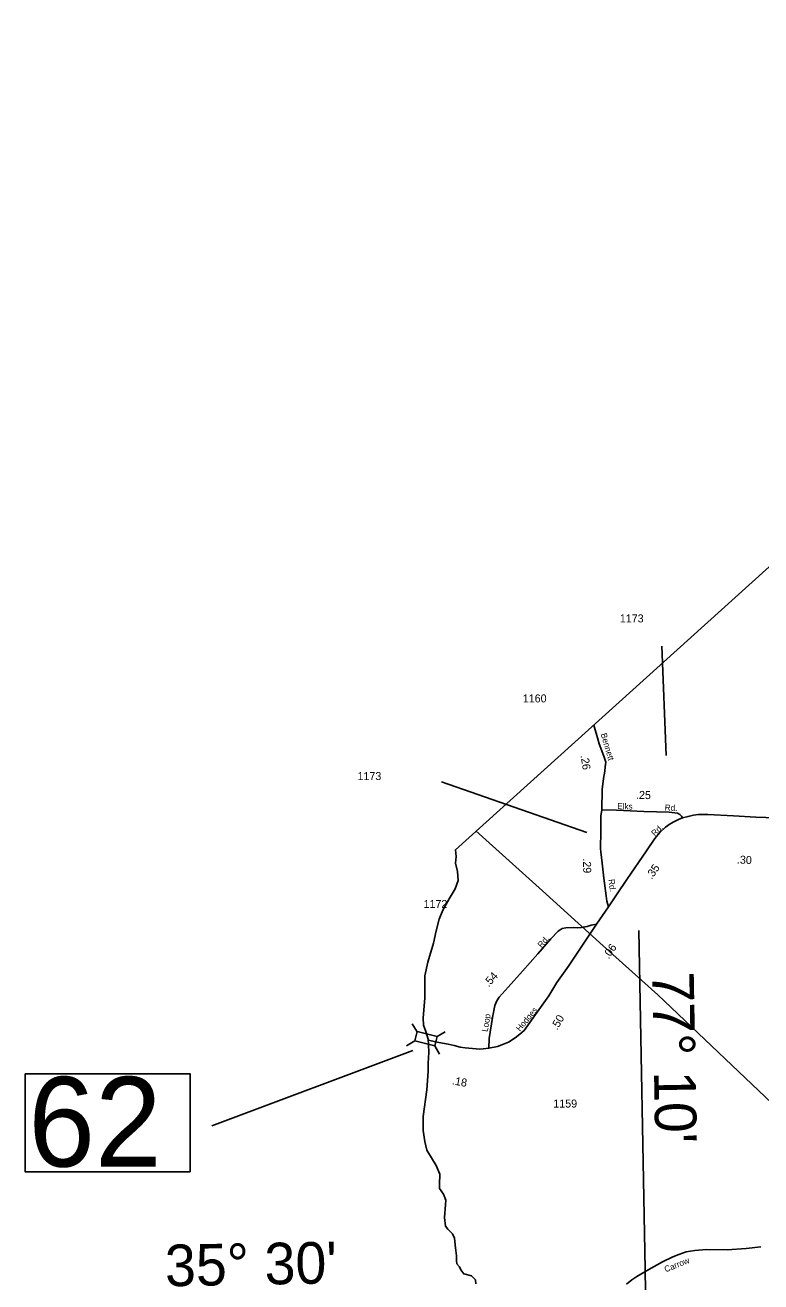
# Model space of a CAD drawing. Extents: x 2532689 to 2764727, y 536648 to 732970.
# Drawn here: x 2535937 to 2547433, y 642091 to 661725 of the extents above; entities that cross this region are included whole.
import ezdxf

# ---------------------------------------------------------------- set-up
doc = ezdxf.new("R2010")
doc.units = 0
for name, color, linetype in [('Exist Boundary Political CountyLine', 7, 'Continuous'), ('Exist Road Secondary Mileage Hundredths English Label', 7, 'Continuous'), ('Exist Road Secondary Structure Standard Bridge CELL', 7, 'Continuous'), ('Exist Road Secondary Structure Standard Bridge Number Label', 7, 'Continuous'), ('Exist Road Secondary Type 20 Attributed', 7, 'Continuous'), ('Exist Road Secondary Type 51 Attributed', 7, 'Continuous'), ('Exist Road Secondary Type 51 Label', 7, 'Continuous'), ('Exist Road Secondary Type 51 Number Label', 7, 'Continuous'), ('Exist Utilities Electrical Transmission Line', 7, 'Continuous'), ('Map Preparation Longitude Latitude Label', 7, 'Continuous'), ('Map Preparation Longitude Latitude Lines', 7, 'Continuous')]:
    doc.layers.add(name, color=color, linetype=linetype)

msp = doc.modelspace()

# ---------------------------------------------------------------- linework, layer by layer
at = {"layer": 'Exist Boundary Political CountyLine'}
for points in [[(2556945, 661725), (2542661, 648841)], [(2542661, 648841), (2542672, 648736), (2542664, 648632), (2542692, 648504), (2542702, 648360), (2542657, 648233), (2542562, 648076), (2542463, 647896), (2542407, 647759), (2542357, 647574), (2542316, 647383), (2542230, 647084), (2542183, 646875), (2542183, 646687), (2542184, 646527), (2542154, 646210), (2542160, 646100), (2542197, 646003), (2542232, 645884), (2542239, 645800), (2542243, 645676), (2542235, 645506), (2542235, 645376), (2542214, 645091), (2542154, 644674), (2542156, 644454), (2542181, 644283), (2542211, 644151), (2542357, 643910), (2542417, 643775), (2542409, 643611), (2542409, 643551), (2542473, 643459), (2542508, 643367), (2542504, 643295), (2542488, 643096), (2542504, 642964), (2542540, 642916), (2542616, 642844), (2542644, 642772), (2542660, 642624), (2542676, 642500), (2542676, 642424), (2542680, 642375), (2542725, 642326), (2542746, 642282), (2542790, 642217), (2542909, 642184), (2542972, 642124), (2542979, 642062)]]:
    msp.add_lwpolyline(points, dxfattribs=at)
at = {"layer": 'Exist Road Secondary Structure Standard Bridge CELL'}
for p, q in [((2542060, 645999), (2541984, 646125)), ((2542499, 645999), (2542373, 645923)), ((2542024, 645856), (2541898, 645781)), ((2542412, 645651), (2542337, 645777))]:
    msp.add_line(p, q, dxfattribs=at)
msp.add_lwpolyline([(2542337, 645777), (2542024, 645856), (2542061, 646001), (2542373, 645923)], close=True, dxfattribs=at)
at = {"layer": 'Exist Road Secondary Structure Standard Bridge Number Label'}
msp.add_line((2541995, 645705), (2538855, 644529), dxfattribs=at)
msp.add_lwpolyline([(2535937, 645343), (2538513, 645343), (2538513, 643813), (2535937, 643813)], close=True, dxfattribs=at)
at = {"layer": 'Exist Road Secondary Type 20 Attributed'}
for points in [[(2545050, 647952), (2545028, 648037), (2545014, 648121), (2544978, 648399), (2544955, 648633), (2544934, 648812), (2544928, 648860), (2544931, 649133), (2544935, 649367), (2544947, 649466)], [(2544947, 649466), (2545175, 649460), (2545605, 649440), (2545999, 649427), (2546129, 649415), (2546167, 649395), (2546194, 649368), (2546209, 649339)], [(2543709, 646945), (2543949, 647217), (2544152, 647449), (2544265, 647570), (2544330, 647610), (2544383, 647622), (2544507, 647630), (2544569, 647624), (2544630, 647627), (2544685, 647636), (2544717, 647642), (2544784, 647663), (2544863, 647682)], [(2543180, 645741), (2543189, 645895), (2543239, 646224), (2543278, 646408), (2543307, 646481), (2543344, 646538), (2543484, 646698), (2543709, 646945)]]:
    msp.add_lwpolyline(points, dxfattribs=at)
at = {"layer": 'Exist Road Secondary Type 51 Attributed'}
for points in [[(2544947, 649466), (2544951, 649781), (2544975, 649955), (2544993, 650068), (2545002, 650138), (2545009, 650209), (2544980, 650303), (2544909, 650495), (2544879, 650591), (2544822, 650790)], [(2546209, 649339), (2546146, 649316), (2546082, 649282), (2546016, 649245), (2545945, 649194), (2545856, 649114), (2545776, 649020), (2545644, 648824), (2545340, 648378), (2545189, 648153), (2545050, 647952)], [(2547824, 649335), (2547356, 649350), (2547008, 649373), (2546603, 649391), (2546451, 649391), (2546378, 649382), (2546295, 649364), (2546209, 649339)], [(2545050, 647952), (2544863, 647682)], [(2544863, 647682), (2544425, 647023), (2544247, 646768), (2544118, 646560), (2543940, 646303), (2543733, 646021), (2543666, 645960), (2543595, 645903), (2543488, 645838), (2543414, 645803), (2543319, 645769), (2543180, 645741)], [(2543180, 645741), (2543094, 645732), (2543043, 645725), (2542813, 645749), (2542733, 645759), (2542642, 645785), (2542547, 645803), (2542399, 645833), (2542233, 645870)], [(2547434, 642638), (2547201, 642614), (2546905, 642593), (2546577, 642597), (2546400, 642582), (2546266, 642561), (2546153, 642521), (2546057, 642483), (2545895, 642402), (2545683, 642286), (2545493, 642173), (2545418, 642122), (2545333, 642056)]]:
    msp.add_lwpolyline(points, dxfattribs=at)
at = {"layer": 'Exist Road Secondary Type 51 Number Label'}
for p, q in [((2545955, 650317), (2545886, 652022)), ((2544715, 649111), (2542441, 649904))]:
    msp.add_line(p, q, dxfattribs=at)
at = {"layer": 'Exist Utilities Electrical Transmission Line'}
msp.add_lwpolyline([(2550484, 642092), (2549562, 642983), (2547817, 644681), (2545822, 646575), (2544971, 647343), (2544019, 648202), (2542980, 649140)], dxfattribs=at)
at = {"layer": 'Map Preparation Longitude Latitude Lines'}
msp.add_line((2545623, 642289), (2545525, 647580), dxfattribs=at)
msp.add_lwpolyline([(2545685, 638934), (2545629, 641941), (2545623, 642289)], dxfattribs=at)

# ---------------------------------------------------------------- texts
at = {"layer": 'Exist Road Secondary Mileage Hundredths English Label'}
for s, rotation, p in [('.26', 278.7111, (2544616, 650313)), ('.25', 358.3698, (2545481, 649639)), ('.30', 357.6239, (2547057, 648628)), ('.29', 271.6923, (2544652, 648706)), ('.35', 54.79, (2545727, 648371)), ('.06', 55.242, (2545055, 647127)), ('.54', 48.4156, (2543180, 646690)), ('.50', 60.0069, (2544251, 646016)), ('.18', 349.474, (2542601, 645179))]:
    msp.add_text(s, height=125, rotation=rotation, dxfattribs=at).set_placement(p)
at = {"layer": 'Exist Road Secondary Structure Standard Bridge Number Label'}
msp.add_text('62', height=1400, dxfattribs=at).set_placement((2535987, 643893))
at = {"layer": 'Exist Road Secondary Type 51 Label'}
for s, rotation, p in [('Bennett', 286.3824, (2544930, 650649)), ('Elks', 358.0994, (2545188, 649478)), ('Rd.', 357.7352, (2545930, 649455)), ('Rd.', 43.6986, (2545775, 649046)), ('Rd.', 277.1923, (2545051, 648377)), ('Rd.', 48.7291, (2544006, 647303)), ('Hodges', 50.167, (2543670, 645997)), ('Loop', 80.381, (2543164, 645992)), ('Carrow', 21.7368, (2545947, 642239))]:
    msp.add_text(s, height=95, rotation=rotation, dxfattribs=at).set_placement(p)
at = {"layer": 'Exist Road Secondary Type 51 Number Label'}
for s, p in [('1173', (2545229, 652394)), ('1160', (2543713, 651144)), ('1173', (2541130, 649931)), ('1172', (2542162, 647932)), ('1159', (2544190, 644815))]:
    msp.add_text(s, height=125, dxfattribs=at).set_placement(p)
at = {"layer": 'Map Preparation Longitude Latitude Label'}
for s, rotation, p in [("77° 10'", 271.0581, (2545734, 646936)), ("35° 30'", 1.0341, (2538127, 642021))]:
    msp.add_text(s, height=650, rotation=rotation, dxfattribs=at).set_placement(p)

doc.saveas('drawing.dxf')
